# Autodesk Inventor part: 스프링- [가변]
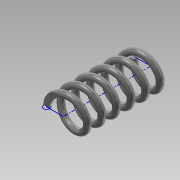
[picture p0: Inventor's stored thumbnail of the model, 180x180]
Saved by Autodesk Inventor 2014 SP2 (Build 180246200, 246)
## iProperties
Created: 2015-12
Part Number: 스프링- [가변]
Material: 강철, 탄소
Document SubType Name: Modeling
Designer: Administrator
Mass: 16.5344 g
Surface Area: 28.5106 cm^2
Volume: 2.10094 cm^3
Density: 7.87 g/cm^3
Appearance: 반연마
Author: Administrator
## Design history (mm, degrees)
sketch "스케치1"
  geometry: L1 (0, 0)-(-8, 0); L2 (-8, 0)-(-8, 42); L3 (-8, 42)-(0, 42); L4 (0, 42)-(0, 0); C1 r 1.5 at (-8, 0)
  constraints: 8 end point, 2 parallel, 1 centre point, 1 coincident, 1 horizontal, 1 perpendicular
  dimensions: "d0" = 16 diameter of L2 L4; "d1" = 42 distance of L3.end L1.start (derived); "d2" = 3 diameter of C1
feature "코일1" sketch "스케치1" pitch "d3" = 10; turns "d5" = 6; dims "d4" = 42 (= d1), "d6" = 0, angle "d7" = 90 deg, angle "d8" = 90 deg, "d9" = 0, "d10" = 0
node "작업 평면1"
feature "분할1"
feature "분할2"
node "솔리드1"
other parameters: "d11" = 44
